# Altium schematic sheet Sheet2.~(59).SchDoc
size A3
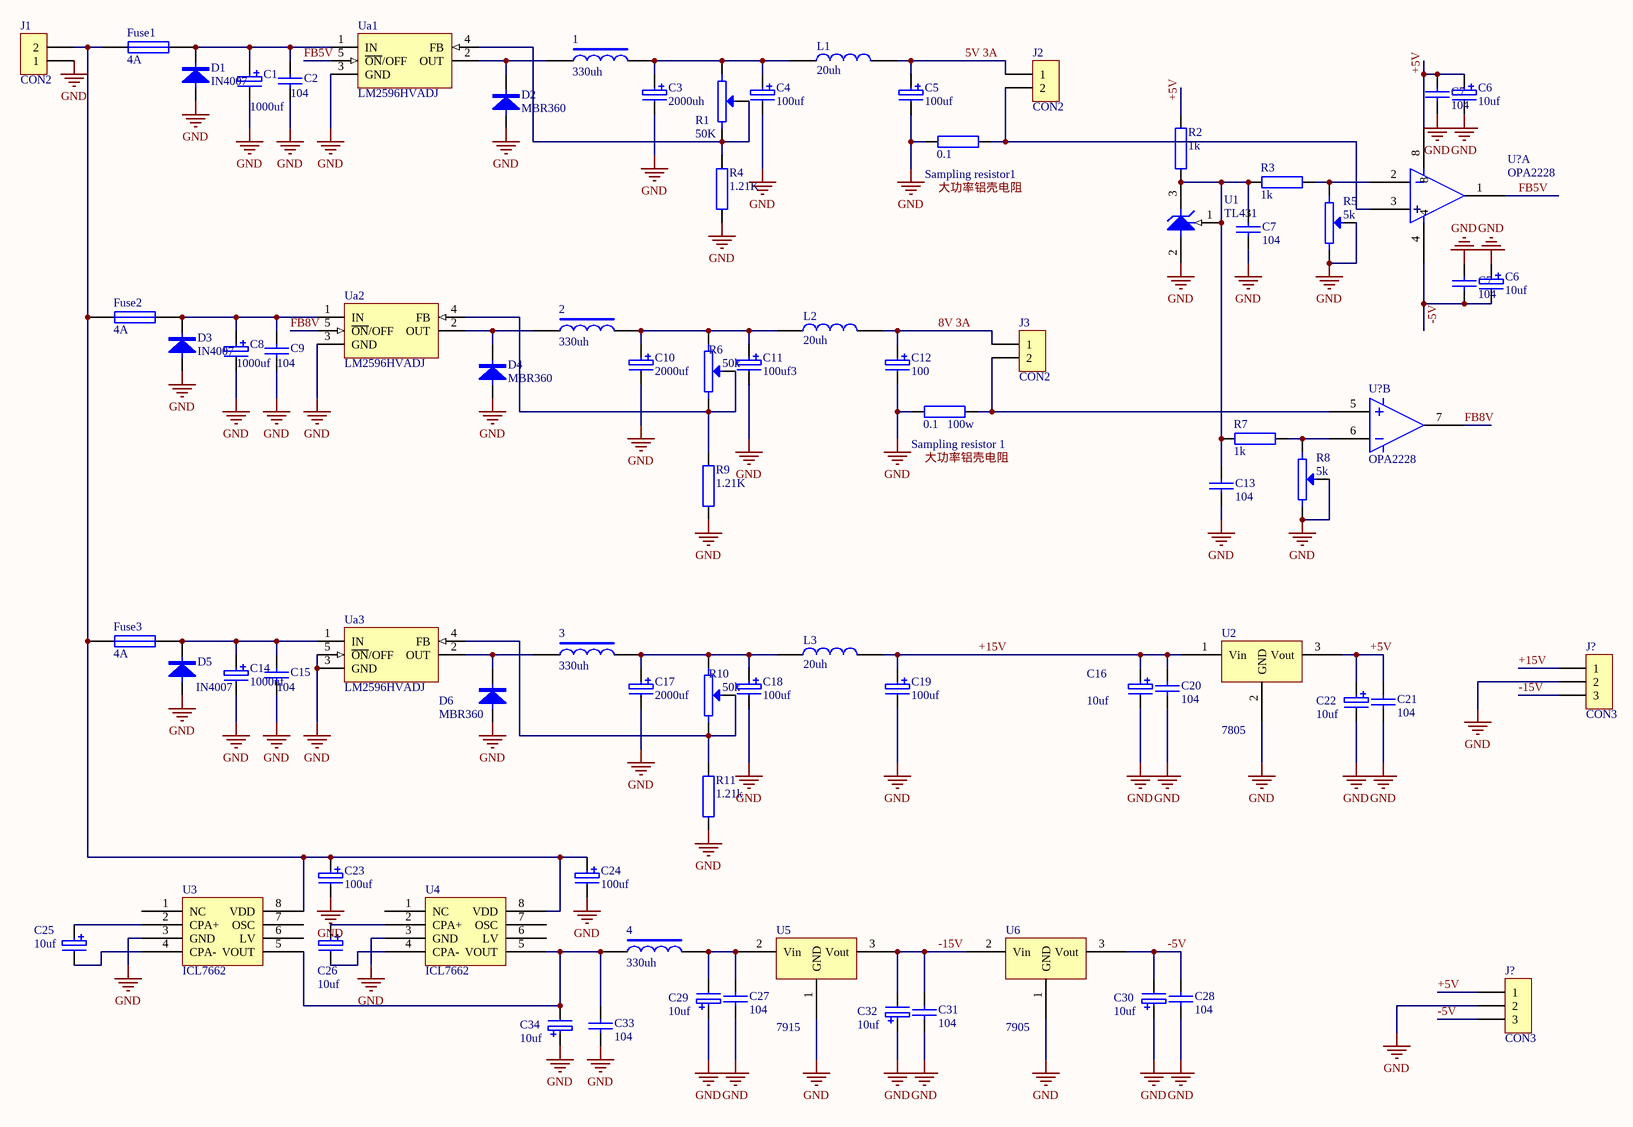
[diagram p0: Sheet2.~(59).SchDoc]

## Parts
(Parts that share a designator on the sheet are numbered #1, #2 ... from top to bottom, then left to right.)
1  330uh  [L]
2  330uh  [L]
3  330uh  [L]
4  330uh  [L]
C1  1000uf  [RB2]
C2  104  [RAD0.2]
C3  2000uh  [RB3]
C4  100uf  [RB3]
C5  100uf  [RB1]
C6#1  10uf  [RB1]
C6#2  10uf  [RB1]
C7#1  104  [RAD0.15]
C7#2  104  [RAD0.15]
C7#3  104  [RAD0.15]
C8  1000uf  [RB2]
C9  104  [RAD0.2]
C10  2000uf  [RB3]
C11  100uf3  [RB3]
C12  100  [RB1]
C13  104  [RAD0.15]
C14  1000uf  [RB2]
C15  104  [RAD0.2]
C16  10uf  [RB3]
C17  2000uf  [RB3]
C18  100uf  [RB3]
C19  100uf  [RB1]
C20  104  [RAD0.15]
C21  104  [RAD0.15]
C22  10uf  [RB3]
C23  100uf  [RB3]
C24  100uf  [RB3]
C25  10uf  [RB3]
C26  10uf  [RB3]
C27  104  [RAD0.15]
C28  104  [RAD0.15]
C29  10uf  [RB3]
C30  10uf  [RB3]
C31  104  [RAD0.15]
C32  10uf  [RB3]
C33  104  [RAD0.15]
C34  10uf  [RB3]
D1  IN4007  [DIODE0.4]
D2  MBR360  [DIODE0.2]
D3  IN4007  [DIODE0.4]
D4  MBR360  [DIODE0.2]
D5  IN4007  [DIODE0.4]
D6  MBR360  [DIODE0.2]
Fuse1  4A  [RAD0.5]
Fuse2  4A  [RAD0.5]
Fuse3  4A  [RAD0.5]
J1  CON2  [BCON2]
J2  CON2  [BCON2]
J3  CON2  [BCON2]
J?#1  CON3  [sip3]
J?#2  CON3  [sip3]
L1  20uh  [LHF440]
L2  20uh  [LHF440]
L3  20uh  [LHF440]
R1  50K  [VR5]
R2  1k  [AXIAL0.3]
R3  1k  [AXIAL0.3]
R4  1.21K  [AXIAL0.3]
R5  5k  [VR5]
R6  50k  [VR5]
R7  1k  [AXIAL0.3]
R8  5k  [VR5]
R9  1.21K  [AXIAL0.3]
R10  50k  [VR5]
R11  1.21k  [AXIAL0.3]
Sampling_resistor1  0.1  [AXIAL0.8]
Sampling_resistor_1  0.1   100w  [AXIAL0.8]
U1  TL431  [TO92B]
U2  7805  [TO257V]
U3  ICL7662  [DIP-8]
U4  ICL7662  [DIP-8]
U5  7915  [TO257V]
U6  7905  [TO257V]
U?#1  OPA2228  [DIP-8]  (part A of 2)
U?#2  OPA2228  [DIP-8]  (part B of 2)
Ua1  LM2596HVADJ  [SIP-5]
Ua2  LM2596HVADJ  [SIP-5]
Ua3  LM2596HVADJ  [SIP-5]

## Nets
GND: C1.2 C2.2 C3.2 C4.2 C5.2 C6#1.2 C6#2.1 C7#1.2 C7#2.2 C7#3.1 C8.2 C9.2 C10.2 C11.2 C12.2 C13.2 C14.2 C15.2 C16.2 C17.2 C18.2 C19.2 C20.2 C21.2 C22.2 C23.2 C24.2 C27.2 C28.2 C29.1 C30.1 C31.2 C32.1 C33.2 C34.1 D1.1 D2.1 D3.1 D4.1 D5.1 D6.1 J1.1 J?#1.2 J?#2.2 R4.1 R5.2(VT) R5.3 R8.2(VT) R8.3 R9.1 R11.1 Sampling_resistor1.2 Sampling_resistor_1.2 U1.2(A) U2.2(GND) U3.3(GND) U4.3(GND) U5.1(GND) U6.1(GND) Ua1.3(GND) Ua2.3(GND) Ua3.3(GND) Ua3.5(~{ON}/OFF)
5V 3A: C5.1 J2.1 L1.2
8V 3A: C12.1 J3.1 L2.2
+5V: C6#1.1 C7#1.1 C21.1 C22.1 J?#2.1 R2.2 U2.3(Vout) U?#1.8
+15V: C16.1 C19.1 C20.1 J?#1.1 L3.2 U2.1(Vin)
-5V: C6#2.2 C7#3.2 C28.1 C30.2 J?#2.3 U6.3(Vout) U?#1.4
-15V: C31.1 C32.2 J?#1.3 U5.3(Vout) U6.2(Vin)
FB5V: U?#1.1(+) Ua1.5(~{ON}/OFF)
FB8V: U?#2.7 Ua2.5(~{ON}/OFF)
Net1_1: 1.1 D2.2 Ua1.2(OUT)
Net1_2: 1.2 C3.1 C4.1 L1.1 R1.1
Net2_1: 2.1 D4.2 Ua2.2(OUT)
Net2_2: 2.2 C10.1 C11.1 L2.1 R6.1
Net3_1: 3.1 D6.2 Ua3.2(OUT)
Net3_2: 3.2 C17.1 C18.1 L3.1 R10.1
Net4_1: 4.1 C33.1 C34.2 U3.5(VOUT) U4.5(VOUT)
Net4_2: 4.2 C27.1 C29.2 U5.2(Vin)
NetC1_1: C1.1 C2.1 D1.2 Fuse1.1 Ua1.1(IN)
NetC7#2_1: C7#2.1 C13.1 R2.1 R3.1 R7.1 U1.1(REF) U1.3(K)
NetC8_1: C8.1 C9.1 D3.2 Fuse2.1 Ua2.1(IN)
NetC14_1: C14.1 C15.1 D5.2 Fuse3.1 Ua3.1(IN)
NetC23_1: C23.1 C24.1 Fuse1.2 Fuse2.2 Fuse3.2 J1.2 U3.8(VDD) U4.8(VDD)
NetC25_1: C25.1 U3.2(CPA+)
NetC25_2: C25.2 U3.4(CPA-)
NetC26_1: C26.1 U4.2(CPA+)
NetC26_2: C26.2 U4.4(CPA-)
NetJ2_2: J2.2 Sampling_resistor1.1 U?#1.3
NetJ3_2: J3.2 Sampling_resistor_1.1 U?#2.5
NetR1_2: R1.2(VT) R1.3 R4.2 Ua1.4(FB)
NetR3_2: R3.2 R5.1 U?#1.2(-)
NetR6_2: R6.2(VT) R6.3 R9.2 Ua2.4(FB)
NetR7_2: R7.2 R8.1 U?#2.6
NetR10_2: R10.2(VT) R10.3 R11.2 Ua3.4(FB)

Not connected (* = marked no-connect by the designer): U3 1(NC) 6(LV) 7(OSC); U4 1(NC) 6(LV) 7(OSC)

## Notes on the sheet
- Labels drawn without touching a wire or pin: 大功率铝壳电阻

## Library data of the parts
1-4 = INDUCTOR2
C1 C3-C5 C6#1 C6#2 C8 C10-C12 C14 C16-C19 C22-C26 C29 C30 C32 C34 = CAP3
C2 C7#1-C7#3 C9 C13 C15 C20 C21 C27 C28 C31 C33 = CAP1
D1-D6 = DIODE
Fuse1-Fuse3 = FUSE1: Fuse
J1-J3 = CON2: Connector
J?#1 J?#2 = CON3: Connector
L1-L3 = INDUCTOR
R1 R5 R6 R8 R10 = RPOT2: Potentiometer
R2-R4 R7 R9 R11 Sampling_resistor1 Sampling_resistor_1 = RES
U1 = TL431: Programmable Voltage Reference
U2 = 78**
U5 U6 = 79**
U?#1 U?#2 = NE5532
Ua1-Ua3 = LM2596T-5.0: Simple Switcher Power Converter 150 kHz 3A Step Down Voltage Regulator; PackageDocument: 2000; Note: Tab is connected to GND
